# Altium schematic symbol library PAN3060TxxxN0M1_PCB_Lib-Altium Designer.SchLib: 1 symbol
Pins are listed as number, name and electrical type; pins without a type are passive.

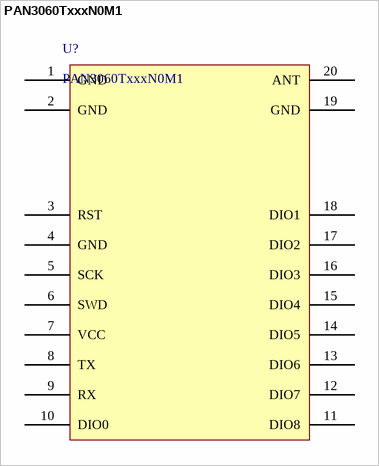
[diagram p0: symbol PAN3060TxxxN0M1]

## PAN3060TxxxN0M1
designator U?
pins: 1 GND, 2 GND, 3 RST, 4 GND, 5 SCK, 6 SWD, 7 VCC, 8 TX, 9 RX, 10 DIO0, 11 DIO8, 12 DIO7, 13 DIO6, 14 DIO5, 15 DIO4, 16 DIO3, 17 DIO2, 18 DIO1, 19 GND, 20 ANT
